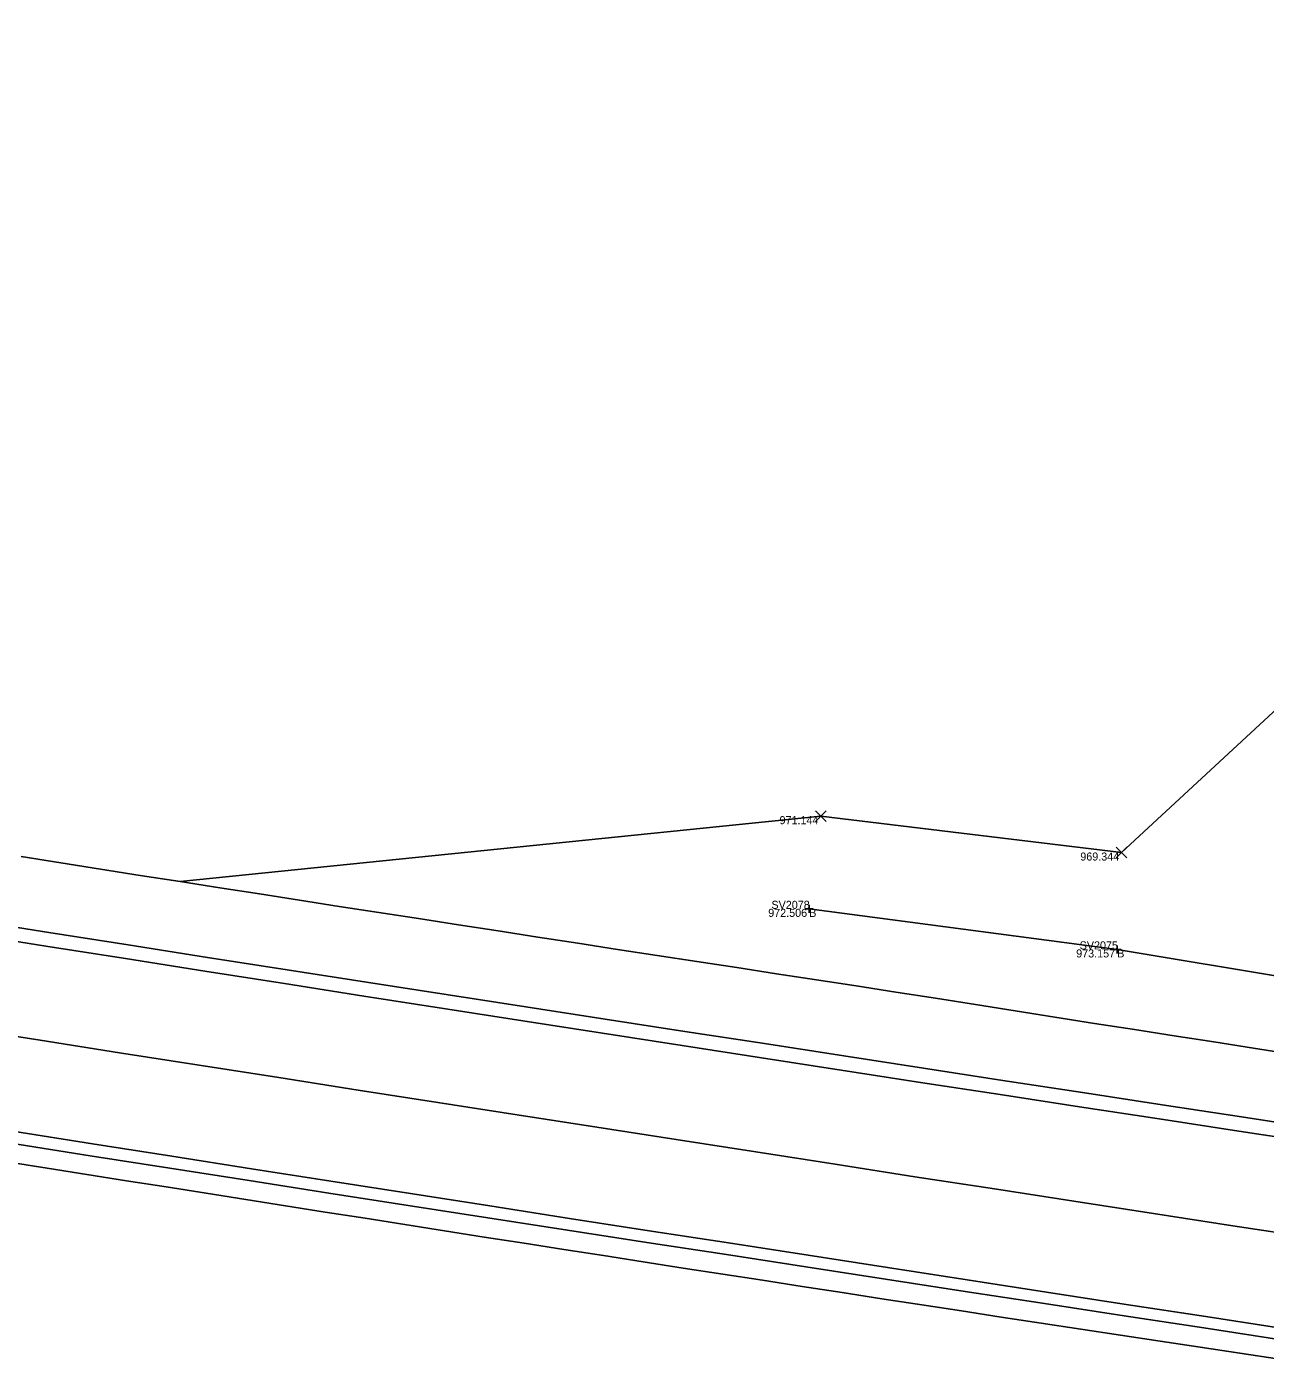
# Model space of a CAD drawing. Extents: x 2065431 to 2068157, y 709104 to 709719.
# Drawn here: x 2066132.9 to 2066286.8, y 709535.6 to 709701.2 of the extents above; entities that cross this region are included whole.
import ezdxf

# ---------------------------------------------------------------- set-up
doc = ezdxf.new("R2010")
doc.units = 0
for name, color, linetype in [('DT_X_Terrain_Boundary', 7, 'Continuous'), ('PM_X_Edge_Line', 7, 'Continuous'), ('PM_X_Lane_Line', 7, 'Continuous'), ('PV_X_EOP', 7, 'Continuous'), ('PV_X_Shoulder_Rumble_Strip', 7, 'Continuous'), ('RS_Raster1', 7, 'Continuous'), ('RW_X_CL_100_Bearings', 7, 'Continuous'), ('SV_X_Break_Lines', 7, 'Continuous'), ('SV_X_Mon_Cells_Found', 7, 'Continuous'), ('SV_X_Text_Elevation', 7, 'Continuous'), ('SV_X_Text_Name', 7, 'Continuous')]:
    doc.layers.add(name, color=color, linetype=linetype)

msp = doc.modelspace()

# ---------------------------------------------------------------- linework, layer by layer
at = {"layer": 'DT_X_Terrain_Boundary'}
msp.add_lwpolyline([(2066649.44, 709584.58), (2066543.44, 709596.37), (2066510.56, 709629.51), (2066507.17, 709644.46), (2066473.93, 709666.44), (2066463.59, 709680.71), (2066437.89, 709682.56), (2066422.56, 709690.18), (2066414.56, 709691.38), (2066359.14, 709688.04), (2066325.73, 709701.2), (2066327.01, 709677.48), (2066325.95, 709651.36), (2066268.91, 709598.56), (2066231.54, 709603.08), (2066151.93, 709594.95), (2066146.99, 709595.72), (2066142.05, 709596.5), (2066137.11, 709597.27), (2066132.17, 709598.05)], dxfattribs=at)
at = {"layer": 'PM_X_Edge_Line'}
for points in [[(2066125.38, 709588.49), (2066135.26, 709586.93), (2066145.14, 709585.37), (2066155.01, 709583.81), (2066164.89, 709582.26), (2066174.77, 709580.71), (2066184.65, 709579.17), (2066194.53, 709577.63), (2066204.42, 709576.1), (2066214.3, 709574.57), (2066224.18, 709573.04), (2066234.06, 709571.52), (2066243.95, 709569.99), (2066253.83, 709568.47), (2066263.71, 709566.95), (2066273.6, 709565.44), (2066283.48, 709563.93), (2066293.37, 709562.43)], [(2066131.16, 709563.93), (2066141.04, 709562.37), (2066150.91, 709560.81), (2066160.79, 709559.26), (2066170.67, 709557.71), (2066180.55, 709556.17), (2066190.43, 709554.63), (2066200.32, 709553.09), (2066210.2, 709551.56), (2066220.08, 709550.04), (2066229.96, 709548.52), (2066239.85, 709546.98), (2066249.73, 709545.45), (2066259.61, 709543.92), (2066269.49, 709542.4), (2066279.38, 709540.88), (2066289.26, 709539.37)]]:
    msp.add_lwpolyline(points, dxfattribs=at)
at = {"layer": 'PM_X_Lane_Line'}
msp.add_lwpolyline([(2066124.67, 709576.79), (2066134.54, 709575.23), (2066144.42, 709573.68), (2066154.3, 709572.12), (2066164.18, 709570.58), (2066174.06, 709569.03), (2066183.94, 709567.49), (2066193.82, 709565.96), (2066203.7, 709564.42), (2066213.59, 709562.89), (2066223.47, 709561.35), (2066233.35, 709559.81), (2066243.23, 709558.27), (2066253.11, 709556.74), (2066262.99, 709555.22), (2066272.88, 709553.7), (2066282.76, 709552.18), (2066292.65, 709550.67)], dxfattribs=at)
at = {"layer": 'PV_X_EOP'}
for points in [[(2066132.17, 709598.05), (2066137.11, 709597.27), (2066142.05, 709596.5), (2066146.99, 709595.72), (2066151.93, 709594.95), (2066156.87, 709594.18), (2066161.81, 709593.41), (2066166.75, 709592.64), (2066171.69, 709591.87), (2066176.63, 709591.1), (2066181.57, 709590.34), (2066186.51, 709589.57), (2066191.45, 709588.81), (2066196.4, 709588.05), (2066201.34, 709587.28), (2066206.28, 709586.52), (2066211.22, 709585.76), (2066216.16, 709585.01), (2066221.11, 709584.25), (2066226.05, 709583.49), (2066230.99, 709582.74), (2066235.93, 709581.99), (2066240.88, 709581.22), (2066245.81, 709580.44), (2066250.75, 709579.66), (2066255.69, 709578.88), (2066260.63, 709578.1), (2066265.57, 709577.32), (2066270.51, 709576.55), (2066275.45, 709575.78), (2066280.39, 709575.01), (2066285.33, 709574.24), (2066290.27, 709573.47)], [(2066130.46, 709560.12), (2066135.4, 709559.33), (2066140.34, 709558.55), (2066145.27, 709557.77), (2066150.21, 709556.99), (2066155.15, 709556.21), (2066160.09, 709555.43), (2066165.03, 709554.65), (2066169.97, 709553.87), (2066174.91, 709553.1), (2066179.85, 709552.32), (2066184.79, 709551.55), (2066189.73, 709550.77), (2066194.67, 709550), (2066199.61, 709549.23), (2066204.55, 709548.46), (2066209.49, 709547.69), (2066214.43, 709546.92), (2066219.37, 709546.16), (2066224.31, 709545.39), (2066229.25, 709544.62), (2066234.19, 709543.86), (2066239.14, 709543.1), (2066244.08, 709542.34), (2066249.02, 709541.59), (2066253.96, 709540.83), (2066258.91, 709540.07), (2066263.85, 709539.32), (2066268.79, 709538.57), (2066273.73, 709537.82), (2066278.68, 709537.07), (2066283.62, 709536.32), (2066288.56, 709535.57)]]:
    msp.add_lwpolyline(points, dxfattribs=at)
at = {"layer": 'PV_X_Shoulder_Rumble_Strip'}
for points in [[(2066125.72, 709590.19), (2066135.6, 709588.63), (2066145.47, 709587.08), (2066155.35, 709585.53), (2066165.23, 709583.98), (2066175.11, 709582.44), (2066185, 709580.91), (2066194.88, 709579.37), (2066204.76, 709577.85), (2066214.64, 709576.32), (2066224.53, 709574.81), (2066234.41, 709573.29), (2066244.3, 709571.77), (2066254.18, 709570.24), (2066264.06, 709568.72), (2066273.95, 709567.2), (2066283.83, 709565.69), (2066293.72, 709564.18)], [(2066130.89, 709562.43), (2066140.77, 709560.88), (2066150.65, 709559.33), (2066160.53, 709557.78), (2066170.41, 709556.23), (2066180.29, 709554.69), (2066190.17, 709553.16), (2066200.05, 709551.63), (2066209.94, 709550.1), (2066219.82, 709548.58), (2066229.7, 709547.06), (2066239.59, 709545.54), (2066249.47, 709544.02), (2066259.35, 709542.5), (2066269.24, 709540.98), (2066279.12, 709539.47), (2066289.01, 709537.97)]]:
    msp.add_lwpolyline(points, dxfattribs=at)
at = {"layer": 'RS_Raster1'}
for p, q in [((2066229.61, 709591.56), (2066230.61, 709591.56)), ((2066230.11, 709592.06), (2066230.11, 709591.06)), ((2066230.11, 709591.56), (2066230.11, 709591.56)), ((2066267.88, 709586.52), (2066268.88, 709586.52)), ((2066268.38, 709587.02), (2066268.38, 709586.02)), ((2066268.38, 709586.52), (2066268.38, 709586.52))]:
    msp.add_line(p, q, dxfattribs=at)
at = {"layer": 'RW_X_CL_100_Bearings'}
for p, q in [((2066230.88, 709602.41), (2066232.21, 709603.75)), ((2066230.88, 709603.75), (2066232.21, 709602.41)), ((2066268.25, 709597.89), (2066269.58, 709599.22)), ((2066268.25, 709599.22), (2066269.58, 709597.89))]:
    msp.add_line(p, q, dxfattribs=at)
at = {"layer": 'SV_X_Break_Lines'}
msp.add_lwpolyline([(2066577.27, 709544.99), (2066531.19, 709548.83), (2066485.96, 709553.92), (2066443.13, 709560.12), (2066391.19, 709568.7), (2066356.03, 709572.66), (2066312.45, 709579.16), (2066268.38, 709586.52), (2066230.11, 709591.56)], dxfattribs=at)

# ---------------------------------------------------------------- texts
at = {"layer": 'SV_X_Mon_Cells_Found'}
for s, p in [('SV2078', (2066225.41, 709591.56)), ('SV2075', (2066263.71, 709586.52))]:
    msp.add_text(s, height=1, dxfattribs=at).set_placement(p)
at = {"layer": 'SV_X_Text_Elevation'}
for p in [(2066230.11, 709590.56), (2066268.38, 709585.52)]:
    msp.add_text('B', height=1, dxfattribs=at).set_placement(p)
at = {"layer": 'SV_X_Text_Name'}
for s, p in [('971.144', (2066226.42, 709602.08)), ('969.344', (2066263.79, 709597.56)), ('972.506', (2066225.01, 709590.56)), ('973.157', (2066263.28, 709585.52))]:
    msp.add_text(s, height=1, dxfattribs=at).set_placement(p)

doc.saveas('drawing.dxf')
